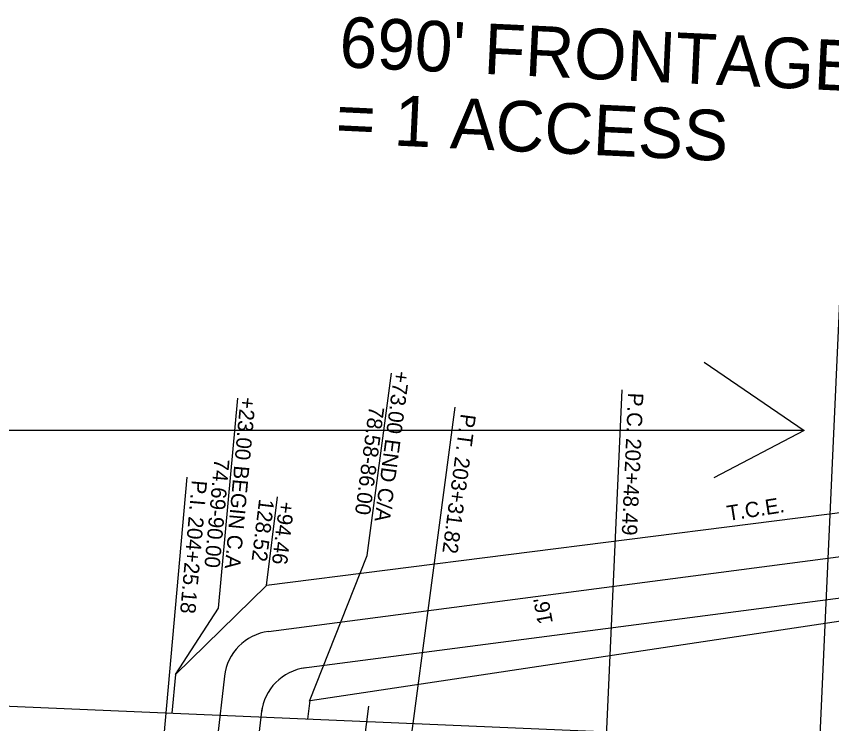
# Model space of a CAD drawing. Extents: x -70 to 701944, y -4 to 666871.
# Drawn here: x 667714.7 to 668034.5, y 656627 to 656904.3 of the extents above; entities that cross this region are included whole.
import ezdxf

# ---------------------------------------------------------------- set-up
doc = ezdxf.new("R2010")
doc.units = 0
for name, color, linetype in [('R_Detour', 7, 'Continuous'), ('R_Drive', 7, 'Continuous'), ('R_Horz Alg Annot', 7, 'Continuous'), ('R_No Plot', 7, 'Continuous'), ('R_ROW', 7, 'Continuous'), ('R_Temp Easement', 7, 'Continuous'), ('R_Temp Easement Annot', 7, 'Continuous')]:
    doc.layers.add(name, color=color, linetype=linetype)

msp = doc.modelspace()

# ---------------------------------------------------------------- linework, layer by layer
at = {"layer": 'R_Detour'}
for p, q in [((668040.77, 656864.8), (668025.83, 656534.26)), ((668023.64, 656741.87), (666796.56, 656741.87)), ((667852.89, 656633.86), (667841.43, 656547.81))]:
    msp.add_line(p, q, dxfattribs=at)
msp.add_lwpolyline([(667984.41, 656768.7), (668023.64, 656741.87), (667988.21, 656723.39)], dxfattribs=at)
at = {"layer": 'R_Drive'}
for p, q in [((667813.65, 656663.15), (668083.67, 656698.47)), ((667826.56, 656648.7), (668085.75, 656682.61)), ((667796.37, 656645.62), (667790.86, 656597.92)), ((667811.01, 656632.92), (667806.84, 656596.86))]:
    msp.add_line(p, q, dxfattribs=at)
for centre in [(667816.24, 656643.32), (667830.7, 656629.07)]:
    msp.add_arc(centre, 20, 97.4523, 173.4041, dxfattribs=at)
at = {"layer": 'R_Horz Alg Annot'}
for points in [[(667942.43, 656538.03), (667952.36, 656757.9)], [(667859.45, 656545.41), (667886.84, 656751.06)], [(667766.92, 656557.74), (667781.69, 656723.66)]]:
    msp.add_lwpolyline(points, dxfattribs=at)
at = {"layer": 'R_ROW'}
msp.add_lwpolyline([(668183.45, 656677.29), (668041.7, 656619.63), (667513.59, 656642.26), (667480, 656629.76), (667392.27, 656637.73), (667276.83, 656674.98), (667204.95, 656679.23), (667093.98, 656660.22), (667018.55, 656674.64), (666944.63, 656677.98), (666832.93, 656665.01), (666352.77, 656716.73), (665777.5, 656723.7), (665727.42, 656722.96), (665452.7, 656735.37), (665090.34, 656757.75), (665090.29, 656778.78), (664696.26, 656796.57), (664695.54, 656784.55), (664566.62, 656799.96)], dxfattribs=at)
at = {"layer": 'R_Temp Easement'}
msp.add_line((667777.16, 656646.27), (667775.76, 656631.03), dxfattribs=at)
for points in [[(668106.78, 656730.6), (668097.47, 656717.27), (667812.86, 656681.2), (667777.16, 656646.27)], [(667829.01, 656628.74), (667829.99, 656636.1), (668086.79, 656674.67)]]:
    msp.add_lwpolyline(points, dxfattribs=at)
at = {"layer": 'R_Temp Easement Annot'}
for points in [[(667829.74, 656635.84), (667852.34, 656692.88), (667861.87, 656764.39)], [(667777.16, 656646.27), (667793.98, 656672.22), (667801.59, 656754.57)], [(667812.86, 656681.2), (667817.08, 656715.95)]]:
    msp.add_lwpolyline(points, dxfattribs=at)

# ---------------------------------------------------------------- texts
at = {"layer": 'R_Drive'}
msp.add_text("16'", height=6, rotation=100.3652, dxfattribs=at).set_placement((667925.16, 656666.56))
at = {"layer": 'R_Horz Alg Annot'}
for s, rotation, p in [('P.C. 202+48.49', 267.413, (667954.66, 656756.84)), ('P.T. 203+31.82', 262.413, (667889.04, 656748.7)), ('P.I. 204+25.18', 264.913, (667783.58, 656722.61))]:
    msp.add_text(s, height=6, rotation=rotation, dxfattribs=at).set_placement(p)
at = {"layer": 'R_No Plot'}
for s, height, p in [("690' FRONTAGE ", 19.8226, (667841.11, 656884.47)), ('= 1 ACCESS', 19.823, (667839.7, 656854.77))]:
    msp.add_text(s, height=height, rotation=357.2978, dxfattribs=at).set_placement(p)
at = {"layer": 'R_Temp Easement Annot'}
for s, rotation, p in [('+73.00 END C/A', 262.4131, (667863.03, 656765.58)), ('+23.00 BEGIN C.A', 264.7203, (667802.66, 656755.25)), ('78.58-86.00', 262.4131, (667853.12, 656751.7)), ('74.69-90.00', 264.7203, (667792.39, 656731.02)), ('128.52', 263.0715, (667809.95, 656715.28)), ('T.C.E.', 8.9029, (667993.84, 656706.44)), ('+94.46', 263.0715, (667817.89, 656714.31))]:
    msp.add_text(s, height=6, rotation=rotation, dxfattribs=at).set_placement(p)

doc.saveas('drawing.dxf')
